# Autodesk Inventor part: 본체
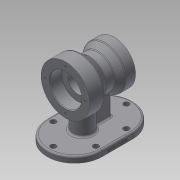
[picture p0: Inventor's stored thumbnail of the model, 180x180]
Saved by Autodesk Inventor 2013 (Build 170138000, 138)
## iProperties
Created: 2020-01
Part Number: 본체
Material: 일반
Document SubType Name: Modeling
Designer: Administrator
Density: 1 g/cm^3
Mass: 347.447 g
Surface Area: 654.888 cm^2
Volume: 347.447 cm^3
Author: Administrator
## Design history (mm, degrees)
sketch "스케치1"
  geometry: L1 (-40, 0)-(40, 0); L2 (-40, 0)-(-40, 26); L3 (-40, 40)-(-16, 40); L4 (-16, 40)-(-1.103, 27.5); L5 (-1.103, 27.5)-(13.289, 27.5); L6 (24, 35)-(40, 35); L7 (40, 35)-(40, 20); L8 (-40, 26)-(-20, 26); L9 (-20, 26)-(-20, 16); L10 (-20, 16)-(23, 16); L11 (23, 16)-(23, 20); L12 (23, 20)-(40, 20); L13 (13.289, 27.5)-(24, 35); L14 (-40, 26)-(-40, 40); L15 (40, 20)-(40, 0); 1 further point
  constraints: 30 end point, 9 perpendicular, 8 parallel, 2 midpoint, 1 horizontal
  dimensions: "d0" = 80 distance of L1.start L1.end; "d3" = 24 distance of L3.start L3.end; "d4" = 16 distance of L6.start L6.end; "d5" = 80 diameter of L3 L1; "d6" = 70 diameter of L6 L1; "d7" = 55 diameter of L5 L1; "d8" = 20 distance of L2.end L8.end; "d9" = 17 distance of L11.end L7.end; "d10" = 52 diameter of L8 L1; "d11" = 40 diameter of L12 L1; "d12" = 32 diameter of L10 L1; "d13" = 40 deg angle of L5 L4; "d14" = 35 deg angle of L13 L5
revolve "회전1" sketch "스케치1" stored, may be unused: angle "d15" = 90 deg
node "작업 평면4"
sketch "스케치4"
  geometry: L1 (-70, 45)-(70, 45); L2 (70, 45)-(70, -45); L3 (70, -45)-(-70, -45); L4 (-70, -45)-(-70, 45); L5 (-70, 45)-(70, -45); L6 (70, 45)-(-70, -45); 1 further point
  constraints: 12 end point, 2 midpoint, 2 parallel, 1 horizontal, 1 perpendicular
  dimensions: "d32" = 140 distance of L1.start L1.end; "d34" = 90 distance of L1.end L2.end
extrude "돌출2" join sketch "스케치4" distance "d35" = 10; taper "d36" = 0 deg
sketch "스케치5"
  geometry: L1 (-70, 45)-(-70, -45) reference; L2 (-12, 5)-(30, 5); L3 (30, 5)-(30, -5); L4 (30, -5)-(-12, -5); L5 (-12, -5)-(-12, 5); L6 (-12, 5)-(30, -5); L7 (30, 5)-(-12, -5); L8 (40, -35)-(40, 35) reference; C1 r 16 at (-12, 0); 4 further points
  constraints: 12 end point, 5 midpoint, 2 horizontal alignment, 2 parallel, 1 centre point, 1 horizontal, 1 perpendicular
  dimensions: "d38" = 58 distance from line of C1.centre L1; "d39" = 10 distance of L2.end L3.end; "d41" = 16 radius of C1; "d42" = 10 distance between parallel lines of L8 L3
extrude "돌출3" join sketch "스케치5" stored distance "d43" = 10; taper "d44" = 0 deg
sketch "스케치6"
  geometry: L1 (140, 0)-(0, 0) reference; L2 (0, 0)-(0, 10) reference; 2 further points
  constraints: 1 other
  dimensions: "d45" = 70 distance from line of point (70, 4) L2; "d46" = 4 distance from line of L1 point (70, 4)
feature "엠보싱1" sketch "스케치6" dims "d0" = 80, "d3" = 24, "d4" = 16, "d5" = 80, "d6" = 70, "d7" = 55, "d8" = 20, "d9" = 17, "d10" = 52, "d11" = 40, "d12" = 32, "d13" = 40 deg, "d14" = 35 deg, "d32" = 140, "d34" = 90, "d47" = 0.5, "d48" = 0
sketch "스케치7"
  geometry: C1 r 20 at (0, 0) reference; 1 further point
  constraints: 1 horizontal alignment
  dimensions: "d49" = 27.5 distance of point (-27.5, 0) C1.centre
hole "구멍1" sketch "스케치7" at (-27.5, 0) diameter "d50" = 3.242; stored, may be unused: countersink angle "d54" = 90 deg, drill point angle "d56" = 118 deg; dims "d51" = 9, "d52" = 4, "d53" = 2, "d55" = 11
sketch "스케치8"
  geometry: C1 r 40 at (0, 0) reference; 1 further point
  constraints: 1 horizontal alignment
  dimensions: "d60" = 33 distance of point (33, 0) C1.centre
hole "구멍2" sketch "스케치8" at (33, 0) diameter "d61" = 3.242; stored, may be unused: countersink angle "d65" = 90 deg, drill point angle "d67" = 118 deg; dims "d62" = 9, "d63" = 4, "d64" = 2, "d66" = 11
sketch "스케치9"
  geometry: L1 (70, 45)-(-70, 45) reference; 2 further points
  dimensions: "d71" = 10 distance from line of L1 point (25, 35); "d72" = 25 horizontal distance of point (25, 35) point (0, 0)
hole "구멍3" sketch "스케치9" at (25, 35) diameter "d73" = 9; stored, may be unused: countersink angle "d77" = 90 deg, drill point angle "d79" = 0 deg; dims "d74" = 9, "d75" = 4, "d76" = 2, "d78" = 11
sketch "스케치10"
  geometry: L1 (-70, 45)-(-70, -45) reference; 2 further points
  constraints: 1 horizontal alignment
  dimensions: "d83" = 10 distance from line of L1 point (-60, 0)
hole "구멍4" sketch "스케치10" at (-60, 0) diameter "d84" = 9; stored, may be unused: countersink angle "d88" = 90 deg, drill point angle "d90" = 0 deg; dims "d85" = 9, "d86" = 4, "d87" = 2, "d89" = 11
fillet "모깎기1" dims "d91" = 45
chamfer "모따기1" distance "d92" = 1; stored, may be unused: second distance "d93" = 2, angle "d94" = 45 deg
fillet "모깎기2" dims "d95" = 0.3
fillet "모깎기3" dims "d96" = 3
fillet "모깎기4" dims "d97" = 3
node "솔리드1"
pattern_circular "원형 패턴1" dims angle "d58" = 360 deg
pattern_circular "원형 패턴2" dims angle "d69" = 360 deg
pattern_linear "직사각형 패턴1" dims "d82" = 50
mirror "대칭1"
mirror "대칭2"
